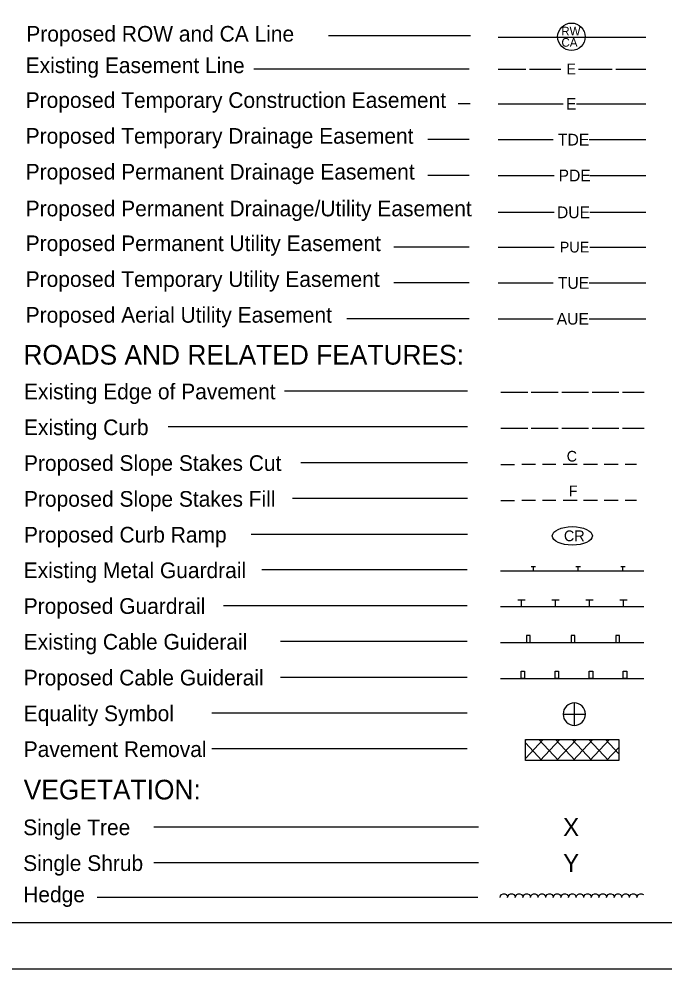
# Model space of a CAD drawing. Extents: x 573077.9 to 573111.9, y -55204.3 to -55182.3.
# Drawn here: x 573089.24 to 573096.46, y -55204.3 to -55193.68 of the extents above; entities that cross this region are included whole.
import ezdxf

# ---------------------------------------------------------------- set-up
doc = ezdxf.new("R2010")
doc.units = 0
for name, color, linetype in [('Prop Easement Permanent Drainage Utility', 7, 'Continuous'), ('Prop WCC CELL', 7, 'Continuous'), ('Sheet Plot Border Inside CELL', 7, 'Continuous'), ('Sheet Symbology CELL', 7, 'Continuous')]:
    doc.layers.add(name, color=color, linetype=linetype)

msp = doc.modelspace()

# ---------------------------------------------------------------- linework, layer by layer
at = {"layer": 'Prop Easement Permanent Drainage Utility'}
for p, q in [((573094.592, -55195.843), (573095.218, -55195.843)), ((573095.618, -55195.843), (573096.242, -55195.843))]:
    msp.add_line(p, q, dxfattribs=at)
at = {"layer": 'Prop WCC CELL'}
msp.add_ellipse((573095.422, -55199.459), major_axis=(0.224, 0), ratio=0.462467, dxfattribs=at)
at = {"layer": 'Sheet Plot Border Inside CELL'}
msp.add_lwpolyline([(573077.854, -55204.298), (573111.854, -55204.298), (573111.854, -55182.298), (573077.854, -55182.298)], close=True, dxfattribs=at)
at = {"layer": 'Sheet Symbology CELL'}
for p, q in [((573094.284, -55193.87), (573092.697, -55193.87)), ((573094.592, -55193.885), (573096.242, -55193.885)), ((573094.271, -55194.242), (573091.866, -55194.242)), ((573094.592, -55194.242), (573094.902, -55194.242)), ((573094.942, -55194.242), (573095.292, -55194.242)), ((573095.492, -55194.242), (573095.867, -55194.242)), ((573095.907, -55194.242), (573096.242, -55194.242)), ((573094.279, -55194.631), (573094.145, -55194.631)), ((573094.592, -55194.631), (573094.644, -55194.631)), ((573094.644, -55194.631), (573095.319, -55194.631)), ((573095.469, -55194.631), (573096.144, -55194.631)), ((573096.144, -55194.631), (573096.242, -55194.631)), ((573094.271, -55195.031), (573093.808, -55195.031)), ((573094.592, -55195.031), (573094.659, -55195.031)), ((573094.659, -55195.031), (573095.209, -55195.031)), ((573095.609, -55195.031), (573096.159, -55195.031)), ((573096.159, -55195.031), (573096.242, -55195.031)), ((573094.271, -55195.431), (573093.808, -55195.431)), ((573094.592, -55195.431), (573094.668, -55195.431)), ((573094.668, -55195.431), (573095.218, -55195.431)), ((573095.618, -55195.431), (573096.168, -55195.431)), ((573096.168, -55195.431), (573096.242, -55195.431)), ((573094.271, -55196.232), (573093.428, -55196.232)), ((573094.592, -55196.232), (573094.669, -55196.232)), ((573094.669, -55196.232), (573095.219, -55196.232)), ((573095.619, -55196.232), (573096.169, -55196.232)), ((573096.169, -55196.232), (573096.242, -55196.232)), ((573094.271, -55196.632), (573093.428, -55196.632)), ((573094.592, -55196.632), (573094.659, -55196.632)), ((573094.659, -55196.632), (573095.209, -55196.632)), ((573095.609, -55196.632), (573096.159, -55196.632)), ((573096.159, -55196.632), (573096.242, -55196.632)), ((573094.271, -55197.032), (573092.902, -55197.032)), ((573094.592, -55197.032), (573094.659, -55197.032)), ((573094.659, -55197.032), (573095.209, -55197.032)), ((573095.609, -55197.032), (573096.159, -55197.032)), ((573096.159, -55197.032), (573096.242, -55197.032)), ((573094.252, -55197.842), (573092.205, -55197.842)), ((573094.623, -55197.854), (573094.923, -55197.854)), ((573094.963, -55197.854), (573095.263, -55197.854)), ((573095.303, -55197.854), (573095.603, -55197.854)), ((573095.643, -55197.854), (573095.943, -55197.854)), ((573095.983, -55197.854), (573096.223, -55197.854)), ((573094.252, -55198.242), (573090.909, -55198.242)), ((573094.623, -55198.254), (573094.923, -55198.254)), ((573094.963, -55198.254), (573095.263, -55198.254)), ((573095.303, -55198.254), (573095.603, -55198.254)), ((573095.643, -55198.254), (573095.943, -55198.254)), ((573095.983, -55198.254), (573096.223, -55198.254)), ((573094.252, -55198.642), (573092.388, -55198.642)), ((573094.623, -55198.663), (573094.775, -55198.663)), ((573095.009, -55198.663), (573094.858, -55198.663)), ((573095.239, -55198.663), (573095.087, -55198.663)), ((573095.474, -55198.663), (573095.318, -55198.663)), ((573095.703, -55198.663), (573095.548, -55198.663)), ((573095.934, -55198.663), (573095.777, -55198.663)), ((573096.14, -55198.663), (573096.012, -55198.663)), ((573094.252, -55199.042), (573092.297, -55199.042)), ((573094.623, -55199.063), (573094.775, -55199.063)), ((573095.009, -55199.063), (573094.858, -55199.063)), ((573095.239, -55199.063), (573095.087, -55199.063)), ((573095.474, -55199.063), (573095.318, -55199.063)), ((573095.703, -55199.063), (573095.548, -55199.063)), ((573095.934, -55199.063), (573095.777, -55199.063)), ((573096.14, -55199.063), (573096.012, -55199.063)), ((573094.252, -55199.442), (573091.833, -55199.442)), ((573094.962, -55199.801), (573095.012, -55199.801)), ((573094.987, -55199.851), (573094.987, -55199.801)), ((573095.462, -55199.801), (573095.512, -55199.801)), ((573095.487, -55199.851), (573095.487, -55199.801)), ((573095.962, -55199.801), (573096.012, -55199.801)), ((573095.987, -55199.851), (573095.987, -55199.801)), ((573094.249, -55199.84), (573091.952, -55199.84)), ((573094.619, -55199.851), (573096.219, -55199.851)), ((573094.249, -55200.24), (573091.524, -55200.24)), ((573094.814, -55200.172), (573094.894, -55200.172)), ((573094.854, -55200.251), (573094.854, -55200.172)), ((573095.194, -55200.172), (573095.274, -55200.172)), ((573095.234, -55200.251), (573095.234, -55200.172)), ((573095.574, -55200.172), (573095.654, -55200.172)), ((573095.614, -55200.251), (573095.614, -55200.172)), ((573095.954, -55200.172), (573096.034, -55200.172)), ((573095.994, -55200.251), (573095.994, -55200.172)), ((573096.219, -55200.251), (573094.619, -55200.251)), ((573094.249, -55200.64), (573092.163, -55200.64)), ((573094.619, -55200.651), (573096.219, -55200.651)), ((573094.249, -55201.04), (573092.163, -55201.04)), ((573094.619, -55201.051), (573096.219, -55201.051)), ((573095.444, -55201.326), (573095.444, -55201.451)), ((573094.249, -55201.44), (573091.396, -55201.44)), ((573095.319, -55201.451), (573095.444, -55201.451)), ((573095.444, -55201.451), (573095.444, -55201.576)), ((573095.444, -55201.451), (573095.569, -55201.451)), ((573094.898, -55201.734), (573095.94, -55201.734)), ((573094.898, -55201.968), (573094.898, -55201.734)), ((573094.898, -55201.746), (573094.909, -55201.734)), ((573094.898, -55201.945), (573095.095, -55201.734)), ((573095.083, -55201.968), (573094.898, -55201.77)), ((573095.269, -55201.968), (573095.049, -55201.734)), ((573095.061, -55201.968), (573095.281, -55201.734)), ((573095.454, -55201.968), (573095.235, -55201.734)), ((573095.246, -55201.968), (573095.467, -55201.734)), ((573095.64, -55201.968), (573095.42, -55201.734)), ((573095.432, -55201.968), (573095.652, -55201.734)), ((573095.826, -55201.968), (573095.605, -55201.734)), ((573095.618, -55201.968), (573095.837, -55201.734)), ((573095.94, -55201.893), (573095.791, -55201.734)), ((573095.803, -55201.968), (573095.94, -55201.822)), ((573095.94, -55201.734), (573095.94, -55201.968)), ((573094.249, -55201.84), (573091.396, -55201.84)), ((573095.94, -55201.968), (573094.898, -55201.968)), ((573094.372, -55202.713), (573090.749, -55202.713)), ((573094.372, -55203.113), (573090.749, -55203.113)), ((573094.366, -55203.498), (573090.113, -55203.498)), ((573094.614, -55203.498), (573094.62, -55203.479)), ((573094.62, -55203.479), (573094.632, -55203.466)), ((573094.632, -55203.466), (573094.648, -55203.457)), ((573094.648, -55203.457), (573094.667, -55203.457)), ((573094.667, -55203.457), (573094.683, -55203.467)), ((573094.683, -55203.467), (573094.694, -55203.48)), ((573094.694, -55203.48), (573094.698, -55203.497)), ((573094.699, -55203.498), (573094.705, -55203.479)), ((573094.705, -55203.479), (573094.717, -55203.466)), ((573094.717, -55203.466), (573094.733, -55203.457)), ((573094.733, -55203.457), (573094.752, -55203.457)), ((573094.752, -55203.457), (573094.768, -55203.467)), ((573094.768, -55203.467), (573094.779, -55203.48)), ((573094.779, -55203.48), (573094.783, -55203.497)), ((573094.784, -55203.498), (573094.79, -55203.479)), ((573094.79, -55203.479), (573094.802, -55203.466)), ((573094.802, -55203.466), (573094.818, -55203.457)), ((573094.818, -55203.457), (573094.837, -55203.457)), ((573094.837, -55203.457), (573094.853, -55203.467)), ((573094.853, -55203.467), (573094.864, -55203.48)), ((573094.864, -55203.48), (573094.868, -55203.497)), ((573094.869, -55203.498), (573094.875, -55203.479)), ((573094.875, -55203.479), (573094.887, -55203.466)), ((573094.887, -55203.466), (573094.903, -55203.457)), ((573094.903, -55203.457), (573094.922, -55203.457)), ((573094.922, -55203.457), (573094.938, -55203.467)), ((573094.938, -55203.467), (573094.949, -55203.48)), ((573094.949, -55203.48), (573094.953, -55203.497)), ((573094.954, -55203.498), (573094.96, -55203.479)), ((573094.96, -55203.479), (573094.972, -55203.466)), ((573094.972, -55203.466), (573094.988, -55203.457)), ((573094.988, -55203.457), (573095.007, -55203.457)), ((573095.007, -55203.457), (573095.023, -55203.467)), ((573095.023, -55203.467), (573095.034, -55203.48)), ((573095.034, -55203.48), (573095.038, -55203.497)), ((573095.039, -55203.498), (573095.045, -55203.479)), ((573095.045, -55203.479), (573095.057, -55203.466)), ((573095.057, -55203.466), (573095.073, -55203.457)), ((573095.073, -55203.457), (573095.092, -55203.457)), ((573095.092, -55203.457), (573095.108, -55203.467)), ((573095.108, -55203.467), (573095.119, -55203.48)), ((573095.119, -55203.48), (573095.123, -55203.497)), ((573095.124, -55203.498), (573095.13, -55203.479)), ((573095.13, -55203.479), (573095.142, -55203.466)), ((573095.142, -55203.466), (573095.158, -55203.457)), ((573095.158, -55203.457), (573095.177, -55203.457)), ((573095.177, -55203.457), (573095.193, -55203.467)), ((573095.193, -55203.467), (573095.204, -55203.48)), ((573095.204, -55203.48), (573095.208, -55203.497)), ((573095.209, -55203.498), (573095.215, -55203.479)), ((573095.215, -55203.479), (573095.227, -55203.466)), ((573095.227, -55203.466), (573095.243, -55203.457)), ((573095.243, -55203.457), (573095.262, -55203.457)), ((573095.262, -55203.457), (573095.278, -55203.467)), ((573095.278, -55203.467), (573095.289, -55203.48)), ((573095.289, -55203.48), (573095.293, -55203.497)), ((573095.294, -55203.498), (573095.3, -55203.479)), ((573095.3, -55203.479), (573095.312, -55203.466)), ((573095.312, -55203.466), (573095.328, -55203.457)), ((573095.328, -55203.457), (573095.347, -55203.457)), ((573095.347, -55203.457), (573095.363, -55203.467)), ((573095.363, -55203.467), (573095.374, -55203.48)), ((573095.374, -55203.48), (573095.378, -55203.497)), ((573095.379, -55203.498), (573095.385, -55203.479)), ((573095.385, -55203.479), (573095.397, -55203.466)), ((573095.397, -55203.466), (573095.413, -55203.457)), ((573095.413, -55203.457), (573095.432, -55203.457)), ((573095.432, -55203.457), (573095.448, -55203.467)), ((573095.448, -55203.467), (573095.459, -55203.48)), ((573095.459, -55203.48), (573095.463, -55203.497)), ((573095.464, -55203.498), (573095.47, -55203.479)), ((573095.47, -55203.479), (573095.482, -55203.466)), ((573095.482, -55203.466), (573095.498, -55203.457)), ((573095.498, -55203.457), (573095.517, -55203.457)), ((573095.517, -55203.457), (573095.533, -55203.467)), ((573095.533, -55203.467), (573095.544, -55203.48)), ((573095.544, -55203.48), (573095.548, -55203.497)), ((573095.549, -55203.498), (573095.555, -55203.479)), ((573095.555, -55203.479), (573095.567, -55203.466)), ((573095.567, -55203.466), (573095.583, -55203.457)), ((573095.583, -55203.457), (573095.602, -55203.457)), ((573095.602, -55203.457), (573095.618, -55203.467)), ((573095.618, -55203.467), (573095.629, -55203.48)), ((573095.629, -55203.48), (573095.633, -55203.497)), ((573095.634, -55203.498), (573095.64, -55203.479)), ((573095.64, -55203.479), (573095.652, -55203.466)), ((573095.652, -55203.466), (573095.668, -55203.457)), ((573095.668, -55203.457), (573095.687, -55203.457)), ((573095.687, -55203.457), (573095.703, -55203.467)), ((573095.703, -55203.467), (573095.714, -55203.48)), ((573095.714, -55203.48), (573095.718, -55203.497)), ((573095.719, -55203.498), (573095.725, -55203.479)), ((573095.725, -55203.479), (573095.737, -55203.466)), ((573095.737, -55203.466), (573095.753, -55203.457)), ((573095.753, -55203.457), (573095.772, -55203.457)), ((573095.772, -55203.457), (573095.788, -55203.467)), ((573095.788, -55203.467), (573095.799, -55203.48)), ((573095.799, -55203.48), (573095.803, -55203.497)), ((573095.804, -55203.498), (573095.81, -55203.479)), ((573095.81, -55203.479), (573095.822, -55203.466)), ((573095.822, -55203.466), (573095.838, -55203.457)), ((573095.838, -55203.457), (573095.857, -55203.457)), ((573095.857, -55203.457), (573095.873, -55203.467)), ((573095.873, -55203.467), (573095.884, -55203.48)), ((573095.884, -55203.48), (573095.888, -55203.497)), ((573095.889, -55203.498), (573095.895, -55203.479)), ((573095.895, -55203.479), (573095.907, -55203.466)), ((573095.907, -55203.466), (573095.923, -55203.457)), ((573095.923, -55203.457), (573095.942, -55203.457)), ((573095.942, -55203.457), (573095.958, -55203.467)), ((573095.958, -55203.467), (573095.969, -55203.48)), ((573095.969, -55203.48), (573095.973, -55203.497)), ((573095.974, -55203.498), (573095.98, -55203.479)), ((573095.98, -55203.479), (573095.992, -55203.466)), ((573095.992, -55203.466), (573096.008, -55203.457)), ((573096.008, -55203.457), (573096.027, -55203.457)), ((573096.027, -55203.457), (573096.043, -55203.467)), ((573096.043, -55203.467), (573096.054, -55203.48)), ((573096.054, -55203.48), (573096.058, -55203.497)), ((573096.059, -55203.498), (573096.065, -55203.479)), ((573096.065, -55203.479), (573096.077, -55203.466)), ((573096.077, -55203.466), (573096.093, -55203.457)), ((573096.093, -55203.457), (573096.112, -55203.457)), ((573096.112, -55203.457), (573096.128, -55203.467)), ((573096.128, -55203.467), (573096.139, -55203.48)), ((573096.139, -55203.48), (573096.143, -55203.497)), ((573096.144, -55203.498), (573096.15, -55203.479)), ((573096.15, -55203.479), (573096.162, -55203.466)), ((573096.162, -55203.466), (573096.178, -55203.457)), ((573096.178, -55203.457), (573096.197, -55203.457)), ((573096.197, -55203.457), (573096.213, -55203.467)), ((573096.213, -55203.467), (573096.214, -55203.468))]:
    msp.add_line(p, q, dxfattribs=at)
for points in [[(573111.354, -55182.798), (573081.354, -55182.798), (573081.354, -55203.778), (573111.354, -55203.778)], [(573094.909, -55200.651), (573094.949, -55200.651), (573094.949, -55200.571), (573094.909, -55200.571)], [(573095.409, -55200.651), (573095.449, -55200.651), (573095.449, -55200.571), (573095.409, -55200.571)], [(573095.909, -55200.651), (573095.949, -55200.651), (573095.949, -55200.571), (573095.909, -55200.571)], [(573094.849, -55200.971), (573094.889, -55200.971), (573094.889, -55201.051), (573094.849, -55201.051)], [(573095.229, -55200.971), (573095.269, -55200.971), (573095.269, -55201.051), (573095.229, -55201.051)], [(573095.609, -55200.971), (573095.649, -55200.971), (573095.649, -55201.051), (573095.609, -55201.051)], [(573095.989, -55200.971), (573096.029, -55200.971), (573096.029, -55201.051), (573095.989, -55201.051)]]:
    msp.add_lwpolyline(points, close=True, dxfattribs=at)
msp.add_circle((573095.412, -55193.882), 0.154, dxfattribs=at)
for start, end in [(89.9944, 179.9989), (359.9944, 89.9989), (179.9944, 269.9989), (269.9944, 359.9989)]:
    msp.add_arc((573095.444, -55201.451), 0.125, start, end, dxfattribs=at)

# ---------------------------------------------------------------- texts
at = {"layer": 'Prop Easement Permanent Drainage Utility'}
msp.add_text('DUE', height=0.131, dxfattribs=at).set_placement((573095.25, -55195.909))
at = {"layer": 'Prop WCC CELL'}
msp.add_text('CR', height=0.12, dxfattribs=at).set_placement((573095.328, -55199.518))
at = {"layer": 'Sheet Symbology CELL'}
for s, height, p in [('Proposed ROW and CA Line', 0.175, (573089.323, -55193.936)), ('RW', 0.0968, (573095.298, -55193.867)), ('CA', 0.0968, (573095.3, -55193.993)), ('Existing Easement Line', 0.175, (573089.316, -55194.288)), ('E', 0.12, (573095.356, -55194.302)), ('Proposed Temporary Construction Easement', 0.175, (573089.316, -55194.677)), ('E', 0.131, (573095.351, -55194.697)), ('Proposed Temporary Drainage Easement', 0.175, (573089.316, -55195.077)), ('TDE', 0.131, (573095.261, -55195.097)), ('Proposed Permanent Drainage Easement', 0.175, (573089.316, -55195.477)), ('PDE', 0.131, (573095.268, -55195.497)), ('Proposed Permanent Drainage/Utility Easement', 0.175, (573089.316, -55195.888)), ('Proposed Permanent Utility Easement', 0.175, (573089.316, -55196.277)), ('PUE', 0.12, (573095.281, -55196.292)), ('Proposed Temporary Utility Easement', 0.175, (573089.316, -55196.677)), ('TUE', 0.131, (573095.26, -55196.698)), ('Proposed Aerial Utility Easement', 0.175, (573089.316, -55197.077)), ('AUE', 0.131, (573095.247, -55197.098)), ('ROADS AND RELATED FEATURES:', 0.22, (573089.291, -55197.545)), ('Existing Edge of Pavement', 0.175, (573089.297, -55197.933)), ('Existing Curb', 0.175, (573089.297, -55198.333)), ('C', 0.119, (573095.359, -55198.628)), ('Proposed Slope Stakes Cut', 0.175, (573089.297, -55198.733)), ('Proposed Slope Stakes Fill', 0.175, (573089.297, -55199.133)), ('F', 0.119, (573095.383, -55199.016)), ('Proposed Curb Ramp', 0.175, (573089.297, -55199.533)), ('Existing Metal Guardrail', 0.175, (573089.294, -55199.931)), ('Proposed Guardrail', 0.175, (573089.294, -55200.33)), ('Existing Cable Guiderail', 0.175, (573089.294, -55200.73)), ('Proposed Cable Guiderail', 0.175, (573089.294, -55201.13)), ('Equality Symbol', 0.175, (573089.294, -55201.53)), ('Pavement Removal', 0.175, (573089.294, -55201.93)), ('VEGETATION:', 0.22, (573089.294, -55202.404)), ('Single Tree', 0.175, (573089.288, -55202.803)), ('X', 0.2, (573095.319, -55202.813)), ('Single Shrub', 0.175, (573089.288, -55203.203)), ('Y', 0.2, (573095.319, -55203.213)), ('Hedge', 0.175, (573089.288, -55203.553))]:
    msp.add_text(s, height=height, dxfattribs=at).set_placement(p)

doc.saveas('drawing.dxf')
